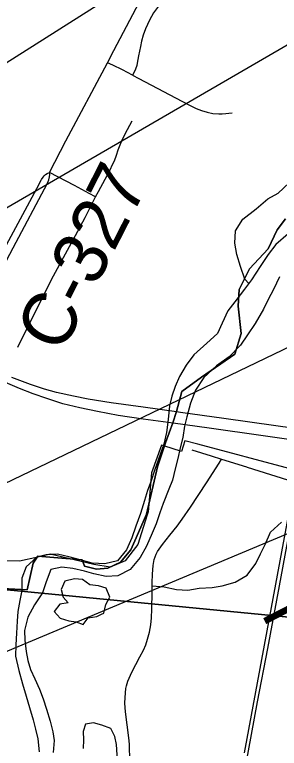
# Model space of a CAD drawing. Extents: x 0 to 34, y 0 to 22.
# Drawn here: x 7.382 to 7.664, y 18.991 to 19.774 of the extents above; entities that cross this region are included whole.
import ezdxf

# ---------------------------------------------------------------- set-up
doc = ezdxf.new("R2010")
doc.units = 0
for name, color, linetype in [('GM_X_City_Street', 7, 'Continuous'), ('GM_X_County_Road', 7, 'Continuous'), ('GM_X_County_Road_Text', 7, 'Continuous'), ('GM_X_Major_River', 7, 'Continuous'), ('GM_X_Minor_Lake', 7, 'Continuous'), ('GM_X_Minor_River', 7, 'Continuous'), ('GM_X_Rail_Line', 7, 'Continuous'), ('GM_X_Section', 7, 'Continuous'), ('GM_X_State_Route', 7, 'Continuous'), ('GM_X_Township_Road', 7, 'Continuous'), ('GM_X_Township_Road_Text', 7, 'Continuous'), ('SC_Shading1', 7, 'Continuous'), ('SH_Text', 7, 'Continuous')]:
    doc.layers.add(name, color=color, linetype=linetype)

msp = doc.modelspace()

# ---------------------------------------------------------------- linework, layer by layer
at = {"layer": 'GM_X_City_Street'}
for points in [[(7.671, 19.55586), (7.66195, 19.54417), (7.65234, 19.52401), (7.63236, 19.50252), (7.62162, 19.48066), (7.62058, 19.4627), (7.62377, 19.43375), (7.61697, 19.41159), (7.58122, 19.38711), (7.56047, 19.37167), (7.55464, 19.35042), (7.55085, 19.33844), (7.54313, 19.31677), (7.5346, 19.29135), (7.5226, 19.24066), (7.51157, 19.2155), (7.50596, 19.20273), (7.49503, 19.18968), (7.48149, 19.18312), (7.46942, 19.18231), (7.45659, 19.18527), (7.45397, 19.19197), (7.42382, 19.19453), (7.40666, 19.19599), (7.402, 19.18865), (7.3953, 19.16012), (7.35554, 19.16229)], [(7.35554, 19.16229), (7.3953, 19.16012), (7.402, 19.18865), (7.40666, 19.19599), (7.42382, 19.19453), (7.45397, 19.19197), (7.45659, 19.18527), (7.46942, 19.18231), (7.48149, 19.18312), (7.49503, 19.18968), (7.50596, 19.20273), (7.51157, 19.2155), (7.5226, 19.24066), (7.5346, 19.29135), (7.54313, 19.31677), (7.55085, 19.33844), (7.55464, 19.35042), (7.56047, 19.37167), (7.58122, 19.38711), (7.61697, 19.41159), (7.62377, 19.43375), (7.62058, 19.4627), (7.62162, 19.48066), (7.63236, 19.50252), (7.65234, 19.52401), (7.66195, 19.54417), (7.671, 19.55586)], [(7.50537, 18.95851), (7.50463, 18.99541), (7.50384, 19.00202), (7.50031, 19.02979), (7.49975, 19.03911), (7.49994, 19.04533), (7.50071, 19.05464), (7.50135, 19.05767), (7.50271, 19.06268), (7.50716, 19.07216), (7.51572, 19.08871), (7.51945, 19.09573), (7.52197, 19.10151), (7.52375, 19.10728), (7.52582, 19.11485), (7.52731, 19.1227), (7.52793, 19.13026), (7.52847, 19.13958), (7.52864, 19.15767), (7.52867, 19.16757), (7.52894, 19.1769), (7.5299, 19.18619), (7.53103, 19.19231), (7.5319, 19.19529), (7.53303, 19.19818), (7.53442, 19.20095), (7.53606, 19.20359), (7.53973, 19.20862), (7.5475, 19.21834), (7.55532, 19.22802), (7.56082, 19.23554), (7.56949, 19.24844), (7.58663, 19.27438), (7.60009, 19.29532), (7.60282, 19.29955)]]:
    msp.add_lwpolyline(points, dxfattribs=at)
at = {"layer": 'GM_X_County_Road'}
for points in [[(7.48109, 19.72253), (7.48777, 19.73566), (7.52523, 19.80656), (7.53878, 19.83237), (7.55436, 19.86218)], [(7.56678, 19.81786), (7.56149, 19.81163), (7.55719, 19.80692), (7.54969, 19.79982), (7.54391, 19.79338), (7.53641, 19.78417), (7.53023, 19.77575), (7.52589, 19.76786), (7.52155, 19.75865), (7.51918, 19.75181), (7.51747, 19.74564), (7.51629, 19.73985), (7.51431, 19.72985), (7.51287, 19.72196), (7.51233, 19.71936), (7.51101, 19.71558), (7.50965, 19.71238), (7.50792, 19.70912)], [(7.41938, 19.60547), (7.43679, 19.63905), (7.48109, 19.72253)], [(7.50792, 19.70912), (7.49706, 19.71489), (7.48695, 19.71973), (7.48109, 19.72253)], [(7.24494, 19.28406), (7.25979, 19.31381), (7.27937, 19.35301), (7.29524, 19.38386), (7.30856, 19.40814), (7.31018, 19.411), (7.31397, 19.41772), (7.33222, 19.44909), (7.37357, 19.52803), (7.40567, 19.58831), (7.41026, 19.59712), (7.41066, 19.59791), (7.41237, 19.60055), (7.41345, 19.6018), (7.41498, 19.6031), (7.41678, 19.60423), (7.41938, 19.60547)], [(7.32163, 19.41383), (7.35119, 19.46947), (7.38041, 19.52488), (7.41717, 19.59412), (7.41859, 19.5975), (7.41932, 19.60089), (7.41955, 19.60316), (7.41938, 19.60547)]]:
    msp.add_lwpolyline(points, dxfattribs=at)
at = {"layer": 'GM_X_Major_River'}
for points in [[(7.6739, 19.53986), (7.66073, 19.52839), (7.65251, 19.51795), (7.64385, 19.50523), (7.63478, 19.49101), (7.62733, 19.48092), (7.61676, 19.46749)], [(7.66446, 19.4941), (7.65806, 19.48057), (7.65249, 19.46968), (7.64731, 19.45955), (7.6386, 19.44417), (7.63034, 19.43221), (7.62286, 19.42098), (7.6108, 19.40872), (7.59729, 19.39916), (7.5837, 19.38656), (7.57503, 19.37309), (7.56976, 19.35915), (7.56562, 19.3448), (7.5631, 19.3346), (7.56129, 19.32248), (7.55875, 19.31152), (7.5562, 19.30018), (7.55329, 19.28922), (7.55034, 19.27713), (7.54669, 19.26734), (7.54063, 19.25227), (7.53698, 19.2421), (7.5329, 19.23041), (7.52887, 19.22062), (7.52284, 19.2067), (7.5161, 19.1947), (7.50516, 19.18165), (7.4921, 19.17512), (7.47956, 19.17428), (7.46672, 19.17724), (7.45655, 19.18014), (7.44408, 19.18272), (7.43235, 19.18414), (7.42053, 19.18176), (7.41566, 19.16857), (7.41196, 19.15687), (7.4033, 19.14415), (7.39616, 19.13102), (7.39278, 19.11665), (7.39291, 19.10638), (7.39451, 19.09418), (7.39618, 19.08464), (7.39899, 19.07507), (7.40368, 19.06507), (7.40873, 19.05393), (7.41266, 19.04395), (7.41619, 19.03284), (7.42005, 19.01983), (7.42282, 19.00874), (7.42411, 18.99921)], [(7.61676, 19.46749), (7.60932, 19.45779), (7.60331, 19.44463), (7.5985, 19.43372), (7.58686, 19.42336), (7.57328, 19.41075), (7.56505, 19.39993), (7.55792, 19.38756), (7.55311, 19.37703), (7.54983, 19.36684), (7.5473, 19.35626), (7.54582, 19.34185), (7.54396, 19.32784), (7.54101, 19.31536), (7.53123, 19.28747), (7.52755, 19.27653), (7.52388, 19.26597), (7.52059, 19.25541), (7.51646, 19.24144), (7.5112, 19.22789), (7.50711, 19.21544), (7.50149, 19.20265), (7.49173, 19.1911), (7.47837, 19.18799), (7.46472, 19.18869), (7.4519, 19.19204), (7.43983, 19.19536), (7.42776, 19.19831), (7.41559, 19.19746), (7.40566, 19.19504), (7.39441, 19.18466), (7.38994, 19.1726), (7.38962, 19.1593), (7.38748, 19.14871), (7.38567, 19.13697), (7.38467, 19.12673), (7.38398, 19.11382), (7.3833, 19.10129), (7.38301, 19.08913), (7.38643, 19.07384), (7.39065, 19.05968), (7.39451, 19.04666), (7.39801, 19.03442), (7.40187, 19.0214), (7.40429, 19.01146), (7.4067, 19.00114), (7.40827, 18.98741)], [(7.42411, 18.99921), (7.42305, 18.98668)]]:
    msp.add_lwpolyline(points, dxfattribs=at)
at = {"layer": 'GM_X_Minor_Lake'}
for points in [[(7.47461, 19.13397), (7.47728, 19.13528), (7.47924, 19.14438), (7.48347, 19.15232), (7.47976, 19.16184), (7.47145, 19.16418), (7.46238, 19.16538), (7.45449, 19.17114), (7.44579, 19.17196), (7.43556, 19.16938)], [(7.43556, 19.16938), (7.4317, 19.1603), (7.43391, 19.15231), (7.43916, 19.1462), (7.43045, 19.14474), (7.42433, 19.13682), (7.43071, 19.12993), (7.43976, 19.12683), (7.4477, 19.12601), (7.45524, 19.12292), (7.4606, 19.13009), (7.46969, 19.13154), (7.47461, 19.13397)], [(7.45781, 19.0166), (7.45511, 19.00903), (7.45541, 18.99992), (7.45534, 18.99081)], [(7.49194, 18.97838), (7.49056, 18.9951), (7.48911, 19.00346), (7.48464, 19.01223), (7.47521, 19.01571), (7.46615, 19.01806), (7.45781, 19.0166)]]:
    msp.add_lwpolyline(points, dxfattribs=at)
at = {"layer": 'GM_X_Minor_River'}
for points in [[(7.63176, 19.48692), (7.62759, 19.49171), (7.62277, 19.50503), (7.61909, 19.51796), (7.61691, 19.53013), (7.61777, 19.54302), (7.62543, 19.55549), (7.63952, 19.56677), (7.65208, 19.5773), (7.6631, 19.58329), (7.67491, 19.5942)], [(7.52858, 19.16451), (7.54143, 19.16327), (7.55465, 19.16052), (7.56675, 19.15967), (7.57887, 19.16185), (7.59287, 19.16251), (7.60348, 19.16433), (7.61713, 19.1684), (7.63005, 19.17589), (7.63922, 19.18835), (7.64422, 19.19857), (7.64922, 19.2084), (7.65499, 19.22164), (7.6668, 19.23218)]]:
    msp.add_lwpolyline(points, dxfattribs=at)
at = {"layer": 'GM_X_Rail_Line'}
for points in [[(6.73244, 20.89996), (6.73558, 20.8782), (6.75257, 20.79657), (6.77176, 20.75571), (6.80444, 20.71734), (6.86223, 20.67506), (6.95222, 20.62273), (7.03048, 20.58139), (7.06553, 20.56464), (7.11106, 20.54569), (7.15491, 20.53375), (7.23618, 20.51761), (7.31988, 20.49303), (7.43844, 20.46855), (7.51371, 20.44121), (7.57645, 20.41309), (7.62966, 20.37962), (7.74184, 20.29969), (7.79545, 20.24366), (7.83539, 20.15953), (7.83526, 20.12527), (7.81886, 20.02519), (7.69091, 19.33091), (7.62688, 18.9861)], [(7.62913, 18.97477), (7.63473, 19.00559), (7.64118, 19.04048), (7.65192, 19.09748), (7.66436, 19.16432), (7.67245, 19.20679), (7.68506, 19.27385), (7.8111, 19.94513), (7.85131, 20.15956), (7.87155, 20.26802), (7.91662, 20.50767), (7.92471, 20.55149), (7.93777, 20.62065), (7.96531, 20.76705), (7.9851, 20.87296), (7.99014, 20.89996)]]:
    msp.add_lwpolyline(points, dxfattribs=at)
at = {"layer": 'GM_X_Section'}
for points in [[(8.36301, 20.07599), (8.27199, 19.07297), (7.26758, 19.17046), (7.35437, 20.16973)], [(7.26758, 19.17046), (8.27199, 19.07297), (8.18593, 18.07293), (7.17505, 18.16824)]]:
    msp.add_lwpolyline(points, close=True, dxfattribs=at)
at = {"layer": 'GM_X_State_Route'}
for points in [[(7.69954, 19.31704), (7.64696, 19.32443), (7.58952, 19.33266), (7.55107, 19.33791), (7.51932, 19.34224), (7.49245, 19.34626), (7.47028, 19.3503), (7.45163, 19.35433), (7.43366, 19.3587), (7.41653, 19.36407), (7.40175, 19.36911), (7.38714, 19.37482), (7.37001, 19.38238)], [(7.70894, 19.32846), (7.66072, 19.33518), (7.60527, 19.34281), (7.55908, 19.3493), (7.55486, 19.34989), (7.51906, 19.35484), (7.48518, 19.35959), (7.46061, 19.36367), (7.44491, 19.36659), (7.42677, 19.37079), (7.41384, 19.37431), (7.39906, 19.37918), (7.37907, 19.38675)]]:
    msp.add_lwpolyline(points, dxfattribs=at)
at = {"layer": 'GM_X_Township_Road'}
for points in [[(7.50792, 19.70912), (7.51469, 19.70556), (7.5672, 19.67784), (7.57565, 19.67377), (7.58145, 19.67145), (7.58742, 19.66964), (7.59355, 19.66846), (7.59978, 19.66795), (7.60355, 19.66789), (7.60715, 19.66816), (7.61039, 19.66856), (7.61422, 19.66914)], [(7.46843, 19.57951), (7.47144, 19.58503), (7.48331, 19.60682), (7.48726, 19.61516), (7.48853, 19.61795), (7.49061, 19.62373), (7.49251, 19.62965), (7.49601, 19.63832), (7.50008, 19.64676), (7.50737, 19.66047)], [(7.46843, 19.57951), (7.46171, 19.58305), (7.4459, 19.59139), (7.41938, 19.60547)], [(7.38568, 19.41893), (7.41603, 19.48037), (7.42369, 19.49508), (7.44688, 19.53817), (7.45718, 19.55742), (7.46399, 19.57088), (7.46552, 19.5738), (7.46843, 19.57951)], [(7.57117, 19.30956), (7.59161, 19.30304), (7.60282, 19.29955)], [(7.60282, 19.29955), (7.62949, 19.29124), (7.63014, 19.29104), (7.68557, 19.2737), (7.70407, 19.26788), (7.71158, 19.26547), (7.72751, 19.26037), (7.74988, 19.2528)]]:
    msp.add_lwpolyline(points, dxfattribs=at)
at = {"layer": 'SC_Shading1'}
msp.add_lwpolyline([(7.67586, 19.28918), (7.5774, 19.31555), (7.56368, 19.31923), (7.56001, 19.30761), (7.54112, 19.31357), (7.53867, 19.31434), (7.52817, 19.28492), (7.52461, 19.24345), (7.52353, 19.24005), (7.51345, 19.20831), (7.49982, 19.19114), (7.4839, 19.18423), (7.46643, 19.18696), (7.42, 19.1981), (7.4067, 19.19509), (7.38715, 19.19068), (7.33952, 19.1918)], dxfattribs=at)
at = {"layer": 'SH_Text'}
for points in [[(9.2218, 20.89411), (4.45803, 17.87452), (9.2218, 20.64169)], [(9.24529, 20.17502), (4.46592, 17.8756), (9.24529, 19.87959)]]:
    msp.add_lwpolyline(points, close=True, dxfattribs=at)

# ---------------------------------------------------------------- texts
at = {"layer": 'GM_X_County_Road_Text'}
msp.add_text('C-327', height=0.056818, rotation=62.96798, dxfattribs=at).set_placement((7.43193, 19.41065))
at = {"layer": 'GM_X_Township_Road_Text'}
msp.add_text('T', height=0.05682, rotation=297.33511, dxfattribs=at).set_placement((7.63811, 19.14729))

doc.saveas('drawing.dxf')
